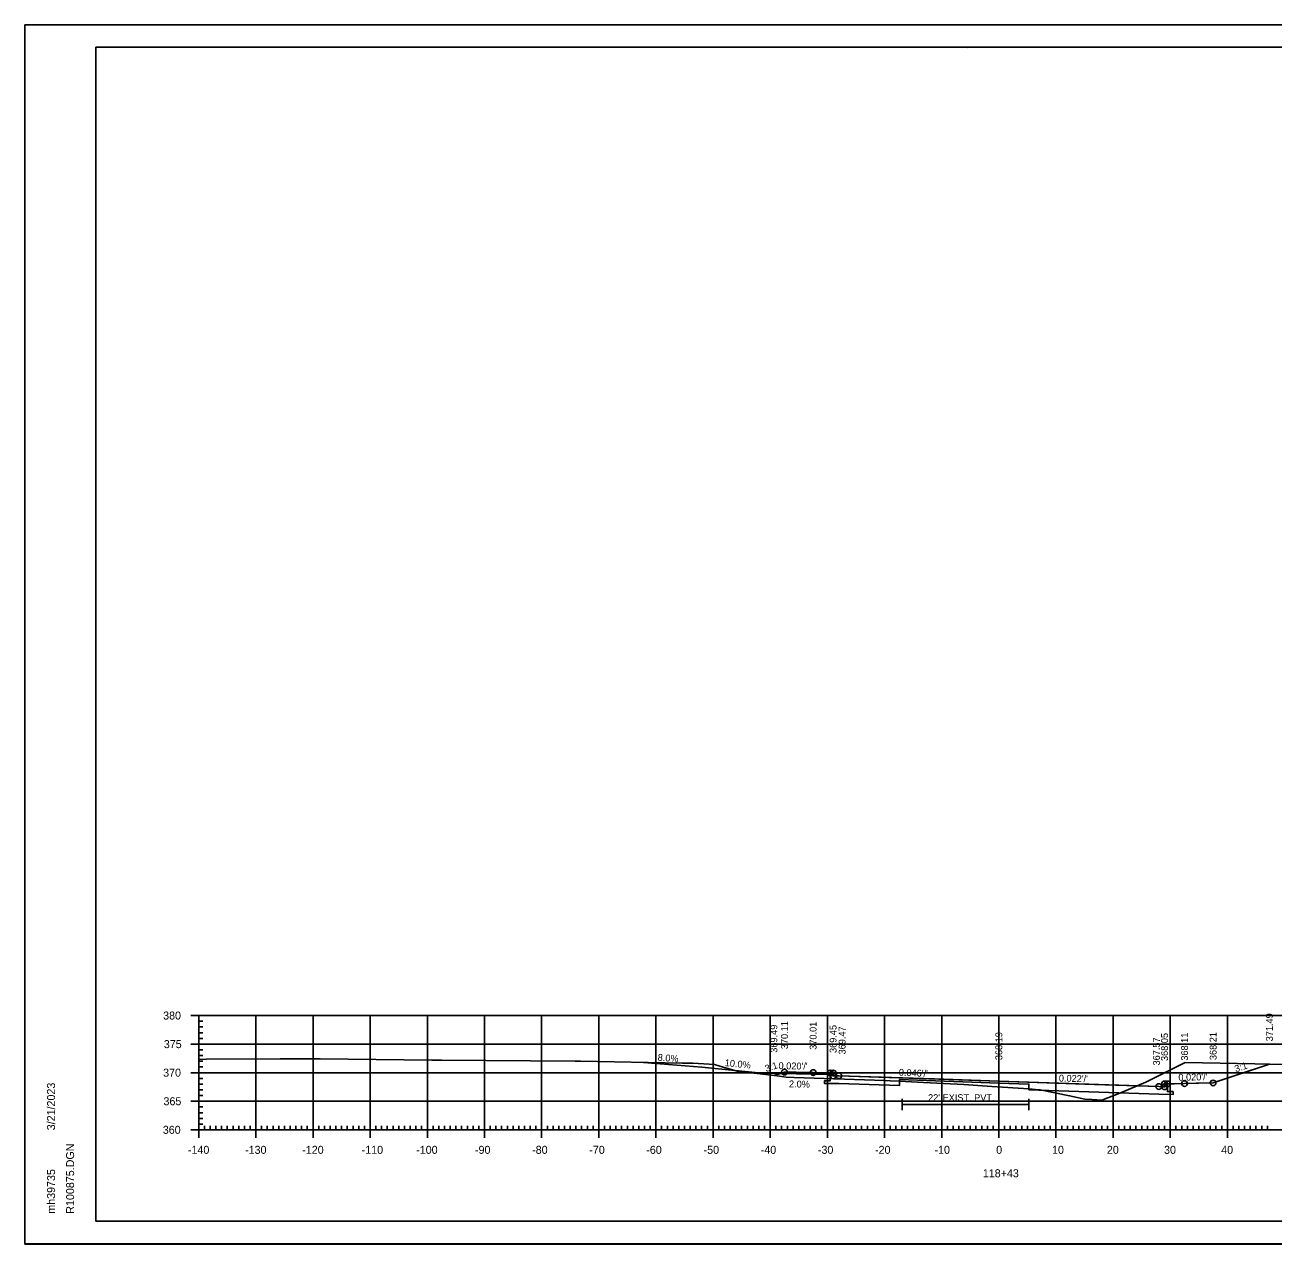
# Model space of a CAD drawing. Extents: x 1368122 to 1710785, y 373130 to 557566.
# Drawn here: x 1368131.6 to 1368350, y 375926.3 to 376139.6 of the extents above; entities that cross this region are included whole.
import ezdxf

# ---------------------------------------------------------------- set-up
doc = ezdxf.new("R2010")
doc.units = 0
for name, color, linetype in [('R_Alt Surface', 7, 'Continuous'), ('R_Axis', 7, 'Continuous'), ('R_Axis Annot', 7, 'Continuous'), ('R_Border', 7, 'Continuous'), ('R_Drive', 7, 'Continuous'), ('R_Exist Surface', 7, 'Continuous'), ('R_Fin Surface', 7, 'Continuous'), ('R_Fin Surface Annot', 7, 'Continuous'), ('R_Grid', 7, 'Continuous'), ('R_No Plot', 7, 'Continuous'), ('R_Proposed Road', 7, 'Continuous'), ('R_Water', 7, 'Continuous'), ('R_Xsect Elev', 7, 'Continuous')]:
    doc.layers.add(name, color=color, linetype=linetype)

msp = doc.modelspace()

# ---------------------------------------------------------------- linework, layer by layer
for points in [[(1368272.5, 375956.2), (1368273, 375956.2), (1368273, 375955.7), (1368274, 375955.72)], [(1368330, 375953.81), (1368331, 375953.79), (1368331, 375954.29), (1368331.5, 375954.29)]]:
    msp.add_lwpolyline(points)
at = {"layer": 'R_Alt Surface'}
for points in [[(1368264.5, 375956.36), (1368262.64, 375955.74)], [(1368331.5, 375954.29), (1368331.5, 375952.95), (1368332.5, 375952.93), (1368332.5, 375952.43), (1368330, 375952.48), (1368307.26, 375953.26), (1368307.26, 375954.26), (1368302, 375954.44), (1368284.64, 375955.03), (1368284.64, 375954.03), (1368274, 375954.38), (1368271.5, 375954.33), (1368271.5, 375954.83), (1368272.5, 375954.85), (1368272.5, 375956.2)], [(1368339.5, 375954.45), (1368349.35, 375957.74)], [(1368285.06, 375951.68), (1368285.06, 375949.68)], [(1368307.26, 375951.68), (1368307.26, 375949.68)], [(1368285.06, 375950.68), (1368307.26, 375950.68)]]:
    msp.add_lwpolyline(points, dxfattribs=at)
at = {"layer": 'R_Axis'}
for p, q in [((1368160.6, 375966.25), (1368163.4, 375966.25)), ((1368162, 375946.25), (1368162, 375966.25)), ((1368162, 375965.25), (1368162.7, 375965.25)), ((1368162, 375964.25), (1368162.7, 375964.25)), ((1368162, 375963.25), (1368162.7, 375963.25)), ((1368162, 375962.25), (1368162.7, 375962.25)), ((1368160.6, 375961.25), (1368163.4, 375961.25)), ((1368162, 375960.25), (1368162.7, 375960.25)), ((1368162, 375959.25), (1368162.7, 375959.25)), ((1368162, 375958.25), (1368162.7, 375958.25)), ((1368160.6, 375956.25), (1368163.4, 375956.25)), ((1368162, 375957.25), (1368162.7, 375957.25)), ((1368162, 375955.25), (1368162.7, 375955.25)), ((1368162, 375954.25), (1368162.7, 375954.25)), ((1368160.6, 375951.25), (1368163.4, 375951.25)), ((1368162, 375953.25), (1368162.7, 375953.25)), ((1368162, 375952.25), (1368162.7, 375952.25)), ((1368162, 375950.25), (1368162.7, 375950.25)), ((1368162, 375949.25), (1368162.7, 375949.25)), ((1368162, 375948.25), (1368162.7, 375948.25)), ((1368162, 375944.85), (1368162, 375947.65)), ((1368162, 375947.25), (1368162.7, 375947.25)), ((1368163, 375946.25), (1368163, 375946.95)), ((1368164, 375946.25), (1368164, 375946.95)), ((1368165, 375946.25), (1368165, 375946.95)), ((1368166, 375946.25), (1368166, 375946.95)), ((1368167, 375946.25), (1368167, 375946.95)), ((1368168, 375946.25), (1368168, 375946.95)), ((1368169, 375946.25), (1368169, 375946.95)), ((1368170, 375946.25), (1368170, 375946.95)), ((1368171, 375946.25), (1368171, 375946.95)), ((1368172, 375944.85), (1368172, 375947.65)), ((1368173, 375946.25), (1368173, 375946.95)), ((1368174, 375946.25), (1368174, 375946.95)), ((1368175, 375946.25), (1368175, 375946.95)), ((1368176, 375946.25), (1368176, 375946.95)), ((1368177, 375946.25), (1368177, 375946.95)), ((1368178, 375946.25), (1368178, 375946.95)), ((1368179, 375946.25), (1368179, 375946.95)), ((1368180, 375946.25), (1368180, 375946.95)), ((1368181, 375946.25), (1368181, 375946.95)), ((1368182, 375944.85), (1368182, 375947.65)), ((1368183, 375946.25), (1368183, 375946.95)), ((1368184, 375946.25), (1368184, 375946.95)), ((1368185, 375946.25), (1368185, 375946.95)), ((1368186, 375946.25), (1368186, 375946.95)), ((1368187, 375946.25), (1368187, 375946.95)), ((1368188, 375946.25), (1368188, 375946.95)), ((1368189, 375946.25), (1368189, 375946.95)), ((1368190, 375946.25), (1368190, 375946.95)), ((1368191, 375946.25), (1368191, 375946.95)), ((1368192, 375944.85), (1368192, 375947.65)), ((1368193, 375946.25), (1368193, 375946.95)), ((1368194, 375946.25), (1368194, 375946.95)), ((1368195, 375946.25), (1368195, 375946.95)), ((1368196, 375946.25), (1368196, 375946.95)), ((1368197, 375946.25), (1368197, 375946.95)), ((1368198, 375946.25), (1368198, 375946.95)), ((1368199, 375946.25), (1368199, 375946.95)), ((1368200, 375946.25), (1368200, 375946.95)), ((1368201, 375946.25), (1368201, 375946.95)), ((1368202, 375944.85), (1368202, 375947.65)), ((1368203, 375946.25), (1368203, 375946.95)), ((1368204, 375946.25), (1368204, 375946.95)), ((1368205, 375946.25), (1368205, 375946.95)), ((1368206, 375946.25), (1368206, 375946.95)), ((1368207, 375946.25), (1368207, 375946.95)), ((1368208, 375946.25), (1368208, 375946.95)), ((1368209, 375946.25), (1368209, 375946.95)), ((1368210, 375946.25), (1368210, 375946.95)), ((1368211, 375946.25), (1368211, 375946.95)), ((1368212, 375944.85), (1368212, 375947.65)), ((1368213, 375946.25), (1368213, 375946.95)), ((1368214, 375946.25), (1368214, 375946.95)), ((1368215, 375946.25), (1368215, 375946.95)), ((1368216, 375946.25), (1368216, 375946.95)), ((1368217, 375946.25), (1368217, 375946.95)), ((1368218, 375946.25), (1368218, 375946.95)), ((1368219, 375946.25), (1368219, 375946.95)), ((1368220, 375946.25), (1368220, 375946.95)), ((1368221, 375946.25), (1368221, 375946.95)), ((1368222, 375944.85), (1368222, 375947.65)), ((1368223, 375946.25), (1368223, 375946.95)), ((1368224, 375946.25), (1368224, 375946.95)), ((1368225, 375946.25), (1368225, 375946.95)), ((1368226, 375946.25), (1368226, 375946.95)), ((1368227, 375946.25), (1368227, 375946.95)), ((1368228, 375946.25), (1368228, 375946.95)), ((1368229, 375946.25), (1368229, 375946.95)), ((1368230, 375946.25), (1368230, 375946.95)), ((1368231, 375946.25), (1368231, 375946.95)), ((1368232, 375944.85), (1368232, 375947.65)), ((1368233, 375946.25), (1368233, 375946.95)), ((1368234, 375946.25), (1368234, 375946.95)), ((1368235, 375946.25), (1368235, 375946.95)), ((1368236, 375946.25), (1368236, 375946.95)), ((1368237, 375946.25), (1368237, 375946.95)), ((1368238, 375946.25), (1368238, 375946.95)), ((1368239, 375946.25), (1368239, 375946.95)), ((1368240, 375946.25), (1368240, 375946.95)), ((1368241, 375946.25), (1368241, 375946.95)), ((1368242, 375944.85), (1368242, 375947.65)), ((1368243, 375946.25), (1368243, 375946.95)), ((1368244, 375946.25), (1368244, 375946.95)), ((1368245, 375946.25), (1368245, 375946.95)), ((1368246, 375946.25), (1368246, 375946.95)), ((1368247, 375946.25), (1368247, 375946.95)), ((1368248, 375946.25), (1368248, 375946.95)), ((1368249, 375946.25), (1368249, 375946.95)), ((1368250, 375946.25), (1368250, 375946.95)), ((1368251, 375946.25), (1368251, 375946.95)), ((1368252, 375944.85), (1368252, 375947.65)), ((1368253, 375946.25), (1368253, 375946.95)), ((1368254, 375946.25), (1368254, 375946.95)), ((1368255, 375946.25), (1368255, 375946.95)), ((1368256, 375946.25), (1368256, 375946.95)), ((1368257, 375946.25), (1368257, 375946.95)), ((1368258, 375946.25), (1368258, 375946.95)), ((1368259, 375946.25), (1368259, 375946.95)), ((1368260, 375946.25), (1368260, 375946.95)), ((1368261, 375946.25), (1368261, 375946.95)), ((1368262, 375944.85), (1368262, 375947.65)), ((1368263, 375946.25), (1368263, 375946.95)), ((1368264, 375946.25), (1368264, 375946.95)), ((1368265, 375946.25), (1368265, 375946.95)), ((1368266, 375946.25), (1368266, 375946.95)), ((1368267, 375946.25), (1368267, 375946.95)), ((1368268, 375946.25), (1368268, 375946.95)), ((1368269, 375946.25), (1368269, 375946.95)), ((1368270, 375946.25), (1368270, 375946.95)), ((1368271, 375946.25), (1368271, 375946.95)), ((1368272, 375944.85), (1368272, 375947.65)), ((1368273, 375946.25), (1368273, 375946.95)), ((1368274, 375946.25), (1368274, 375946.95)), ((1368275, 375946.25), (1368275, 375946.95)), ((1368276, 375946.25), (1368276, 375946.95)), ((1368277, 375946.25), (1368277, 375946.95)), ((1368278, 375946.25), (1368278, 375946.95)), ((1368279, 375946.25), (1368279, 375946.95)), ((1368280, 375946.25), (1368280, 375946.95)), ((1368281, 375946.25), (1368281, 375946.95)), ((1368282, 375944.85), (1368282, 375947.65)), ((1368283, 375946.25), (1368283, 375946.95)), ((1368284, 375946.25), (1368284, 375946.95)), ((1368285, 375946.25), (1368285, 375946.95)), ((1368286, 375946.25), (1368286, 375946.95)), ((1368287, 375946.25), (1368287, 375946.95)), ((1368288, 375946.25), (1368288, 375946.95)), ((1368289, 375946.25), (1368289, 375946.95)), ((1368290, 375946.25), (1368290, 375946.95)), ((1368291, 375946.25), (1368291, 375946.95)), ((1368292, 375944.85), (1368292, 375947.65)), ((1368293, 375946.25), (1368293, 375946.95)), ((1368294, 375946.25), (1368294, 375946.95)), ((1368295, 375946.25), (1368295, 375946.95)), ((1368296, 375946.25), (1368296, 375946.95)), ((1368297, 375946.25), (1368297, 375946.95)), ((1368298, 375946.25), (1368298, 375946.95)), ((1368299, 375946.25), (1368299, 375946.95)), ((1368300, 375946.25), (1368300, 375946.95)), ((1368301, 375946.25), (1368301, 375946.95)), ((1368302, 375944.85), (1368302, 375947.65)), ((1368303, 375946.25), (1368303, 375946.95)), ((1368304, 375946.25), (1368304, 375946.95)), ((1368305, 375946.25), (1368305, 375946.95)), ((1368306, 375946.25), (1368306, 375946.95)), ((1368307, 375946.25), (1368307, 375946.95)), ((1368308, 375946.25), (1368308, 375946.95)), ((1368309, 375946.25), (1368309, 375946.95)), ((1368310, 375946.25), (1368310, 375946.95)), ((1368311, 375946.25), (1368311, 375946.95)), ((1368312, 375944.85), (1368312, 375947.65)), ((1368313, 375946.25), (1368313, 375946.95)), ((1368314, 375946.25), (1368314, 375946.95)), ((1368315, 375946.25), (1368315, 375946.95)), ((1368316, 375946.25), (1368316, 375946.95)), ((1368317, 375946.25), (1368317, 375946.95)), ((1368318, 375946.25), (1368318, 375946.95)), ((1368319, 375946.25), (1368319, 375946.95)), ((1368320, 375946.25), (1368320, 375946.95)), ((1368321, 375946.25), (1368321, 375946.95)), ((1368322, 375944.85), (1368322, 375947.65)), ((1368323, 375946.25), (1368323, 375946.95)), ((1368324, 375946.25), (1368324, 375946.95)), ((1368325, 375946.25), (1368325, 375946.95)), ((1368326, 375946.25), (1368326, 375946.95)), ((1368327, 375946.25), (1368327, 375946.95)), ((1368328, 375946.25), (1368328, 375946.95)), ((1368329, 375946.25), (1368329, 375946.95)), ((1368330, 375946.25), (1368330, 375946.95)), ((1368331, 375946.25), (1368331, 375946.95)), ((1368332, 375944.85), (1368332, 375947.65)), ((1368333, 375946.25), (1368333, 375946.95)), ((1368334, 375946.25), (1368334, 375946.95)), ((1368335, 375946.25), (1368335, 375946.95)), ((1368336, 375946.25), (1368336, 375946.95)), ((1368337, 375946.25), (1368337, 375946.95)), ((1368338, 375946.25), (1368338, 375946.95)), ((1368339, 375946.25), (1368339, 375946.95)), ((1368340, 375946.25), (1368340, 375946.95)), ((1368341, 375946.25), (1368341, 375946.95)), ((1368342, 375944.85), (1368342, 375947.65)), ((1368343, 375946.25), (1368343, 375946.95)), ((1368344, 375946.25), (1368344, 375946.95)), ((1368345, 375946.25), (1368345, 375946.95)), ((1368346, 375946.25), (1368346, 375946.95)), ((1368347, 375946.25), (1368347, 375946.95)), ((1368348, 375946.25), (1368348, 375946.95)), ((1368349, 375946.25), (1368349, 375946.95)), ((1368160.6, 375946.25), (1368163.4, 375946.25)), ((1368162, 375946.25), (1368442, 375946.25))]:
    msp.add_line(p, q, dxfattribs=at)
at = {"layer": 'R_Border'}
for p, q in [((1368144, 376135.71), (1368460.18, 376135.71)), ((1368144, 375930.25), (1368144, 376135.71)), ((1368296.52, 376135.45), (1368296.52, 376135.45)), ((1368296.52, 376135.45), (1368296.52, 376135.45)), ((1368144, 375930.25), (1368144, 375930.25)), ((1368460.18, 375930.25), (1368144, 375930.25))]:
    msp.add_line(p, q, dxfattribs=at)
at = {"layer": 'R_Drive'}
for p, q in [((1368239.84, 375958.05), (1368250.06, 375957.23)), ((1368260.51, 375956.19), (1368250.06, 375957.23)), ((1368272.5, 375955.95), (1368260.51, 375956.19)), ((1368273, 375955.7), (1368272.5, 375955.95))]:
    msp.add_line(p, q, dxfattribs=at)
at = {"layer": 'R_Exist Surface'}
for points in [[(1368162, 375958.58), (1368163.35, 375958.61), (1368176.24, 375958.69), (1368180.2, 375958.66), (1368183.25, 375958.65), (1368202.81, 375958.44), (1368204.47, 375958.42), (1368227.84, 375958.25), (1368227.9, 375958.25), (1368227.95, 375958.25), (1368228.8, 375958.24), (1368246.61, 375957.94), (1368247.2, 375957.93), (1368248.44, 375957.91), (1368252.27, 375957.67), (1368253.76, 375957.23), (1368256.2, 375956.53), (1368263.19, 375955.68), (1368264.81, 375955.47), (1368266.21, 375955.42), (1368281.99, 375954.87), (1368283, 375954.83), (1368284.64, 375954.77), (1368288.8, 375954.53), (1368295.86, 375954.16), (1368300.79, 375953.85), (1368307.26, 375953.44), (1368308.39, 375953.33), (1368309.22, 375953.25), (1368314.38, 375952.22), (1368317.06, 375951.61), (1368318.28, 375951.57), (1368320, 375951.45), (1368323.16, 375952.65), (1368327.7, 375954.6), (1368330.75, 375956.13), (1368334.6, 375958.03), (1368346.81, 375957.8), (1368354.7, 375957.62)], [(1368269.5, 375956.26), (1368272.5, 375956.2)], [(1368331.5, 375954.29), (1368334.5, 375954.35)]]:
    msp.add_lwpolyline(points, dxfattribs=at)
at = {"layer": 'R_Fin Surface'}
for points in [[(1368262.64, 375955.74), (1368263.47, 375956.01), (1368264.5, 375956.36), (1368266.54, 375956.32), (1368269.5, 375956.26), (1368271.28, 375956.22), (1368272.5, 375956.2), (1368272.71, 375956.2), (1368273, 375956.2), (1368273, 375956), (1368273, 375955.7), (1368273.6, 375955.71), (1368274, 375955.72), (1368290.73, 375955.15), (1368302, 375954.77), (1368318.74, 375954.2), (1368330, 375953.81), (1368330.59, 375953.8), (1368331, 375953.79), (1368331, 375954), (1368331, 375954.29), (1368331.21, 375954.29), (1368331.5, 375954.29), (1368332.72, 375954.32), (1368334.5, 375954.35), (1368336.54, 375954.4), (1368339.5, 375954.45), (1368343.52, 375955.79), (1368349.35, 375957.74)], [(1368330, 375953.81), (1368302, 375954.77), (1368274, 375955.72)]]:
    msp.add_lwpolyline(points, dxfattribs=at)
at = {"layer": 'R_Grid'}
for p, q in [((1368162, 375966.25), (1368442, 375966.25)), ((1368162, 375946.25), (1368162, 375966.25)), ((1368172, 375946.25), (1368172, 375966.25)), ((1368182, 375946.25), (1368182, 375966.25)), ((1368192, 375946.25), (1368192, 375966.25)), ((1368202, 375946.25), (1368202, 375966.25)), ((1368212, 375946.25), (1368212, 375966.25)), ((1368222, 375946.25), (1368222, 375966.25)), ((1368232, 375946.25), (1368232, 375966.25)), ((1368242, 375946.25), (1368242, 375966.25)), ((1368252, 375946.25), (1368252, 375966.25)), ((1368262, 375946.25), (1368262, 375966.25)), ((1368272, 375946.25), (1368272, 375966.25)), ((1368282, 375946.25), (1368282, 375966.25)), ((1368292, 375946.25), (1368292, 375966.25)), ((1368302, 375946.25), (1368302, 375966.25)), ((1368312, 375946.25), (1368312, 375966.25)), ((1368322, 375946.25), (1368322, 375966.25)), ((1368332, 375946.25), (1368332, 375966.25)), ((1368342, 375946.25), (1368342, 375966.25)), ((1368162, 375961.25), (1368442, 375961.25)), ((1368162, 375956.25), (1368442, 375956.25)), ((1368162, 375951.25), (1368442, 375951.25)), ((1368162, 375946.25), (1368442, 375946.25))]:
    msp.add_line(p, q, dxfattribs=at)
at = {"layer": 'R_No Plot'}
for p, q in [((1368131.6, 376139.6), (1368464.93, 376139.6)), ((1368131.6, 375926.27), (1368464.93, 375926.27))]:
    msp.add_line(p, q, dxfattribs=at)
for points in [[(1368131.59, 376139.6), (1368464.93, 376139.6), (1368464.93, 375926.26), (1368131.59, 375926.26)], [(1368377.92, 376135.71), (1368397.54, 376135.71), (1368397.54, 376125.83), (1368413.65, 376125.83), (1368436.85, 376125.83), (1368436.97, 376097.67), (1368460.18, 376097.67), (1368460.18, 375930.25), (1368144, 375930.25), (1368144, 376135.71)]]:
    msp.add_lwpolyline(points, close=True, dxfattribs=at)
for centre in [(1368264.5, 375956.36), (1368269.5, 375956.26), (1368272.5, 375956.2), (1368273, 375956.2), (1368273, 375955.7), (1368274, 375955.72), (1368330, 375953.81), (1368331, 375954.29), (1368331, 375953.79), (1368331.5, 375954.29), (1368334.5, 375954.35), (1368339.5, 375954.45)]:
    msp.add_circle(centre, 0.5, dxfattribs=at)
at = {"layer": 'R_Proposed Road'}
for points in [[(1368264.5, 375956.36), (1368269.5, 375956.26)], [(1368334.5, 375954.35), (1368339.5, 375954.45)]]:
    msp.add_lwpolyline(points, dxfattribs=at)

# ---------------------------------------------------------------- texts
at = {"layer": 'R_Axis Annot'}
for s, p in [('380', (1368155.77, 375965.55)), ('375', (1368155.89, 375960.55)), ('370', (1368155.77, 375955.55)), ('365', (1368155.83, 375950.55)), ('360', (1368155.71, 375945.55)), ('-140', (1368160.11, 375942.05)), ('-130', (1368170.11, 375942.05)), ('-120', (1368180.11, 375942.05)), ('-110', (1368190.51, 375942.05)), ('-100', (1368200.05, 375942.05)), ('-90', (1368210.34, 375942.05)), ('-80', (1368220.34, 375942.05)), ('-70', (1368230.34, 375942.05)), ('-60', (1368240.31, 375942.05)), ('-50', (1368250.34, 375942.05)), ('-40', (1368260.34, 375942.05)), ('-30', (1368270.34, 375942.05)), ('-20', (1368280.34, 375942.05)), ('-10', (1368290.74, 375942.05)), ('0', (1368301.54, 375942.05)), ('10', (1368311.31, 375942.05)), ('20', (1368320.91, 375942.05)), ('30', (1368330.91, 375942.05)), ('40', (1368340.91, 375942.05)), ('118+43', (1368299.2, 375937.95))]:
    msp.add_text(s, height=1.4, dxfattribs=at).set_placement(p)
at = {"layer": 'R_Border'}
for s, p in [('3/21/2023', (1368136.86, 375946.17)), ('R100875.DGN', (1368140.19, 375931.57)), ('mh39735', (1368136.86, 375931.57))]:
    msp.add_text(s, height=1.4, rotation=90, dxfattribs=at).set_placement(p)
at = {"layer": 'R_Fin Surface Annot'}
for s, rotation, p in [('371.49', 90, (1368349.95, 375961.74)), ('369.49', 90, (1368263.24, 375959.74)), ('370.11', 90, (1368265.1, 375960.36)), ('370.01', 90, (1368270.1, 375960.26)), ('369.45', 90, (1368273.6, 375959.7)), ('369.47', 90, (1368275.18, 375959.44)), ('368.19', 90, (1368302.6, 375958.44)), ('367.57', 90, (1368330.18, 375957.51)), ('368.05', 90, (1368331.6, 375958.29)), ('368.11', 90, (1368335.1, 375958.35)), ('368.21', 90, (1368340.1, 375958.45)), ('3:1', 18.4348, (1368261.3, 375956.35)), ("0.020'/'", 358.8542, (1368263.45, 375956.88)), ('3:1', 18.435, (1368343.48, 375956.31)), ("0.046'/'", 357.3785, (1368284.48, 375955.74)), ("0.022'/'", 358.7274, (1368312.5, 375954.7)), ("0.020'/'", 1.1458, (1368333.43, 375954.83))]:
    msp.add_text(s, height=1.2, rotation=rotation, dxfattribs=at).set_placement(p)
at = {"layer": 'R_Water'}
msp.add_text("22' EXIST. PVT.", height=1.2, dxfattribs=at).set_placement((1368289.62, 375951.28))
at = {"layer": 'R_Xsect Elev'}
for s, rotation, p in [('8.0%', 355.4261, (1368242.27, 375958.36)), ('10.0%', 354.2894, (1368254, 375957.41)), ('2.0%', 358.8542, (1368265.27, 375953.69))]:
    msp.add_text(s, height=1.2, rotation=rotation, dxfattribs=at).set_placement(p)

doc.saveas('drawing.dxf')
